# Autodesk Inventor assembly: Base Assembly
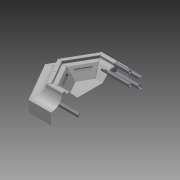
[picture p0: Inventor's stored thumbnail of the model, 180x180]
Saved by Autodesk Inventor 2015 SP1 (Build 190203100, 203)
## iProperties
Created: 2014-12
Part Number: Base Assembly
Document SubType Name: Assembly
Designer: rsheridan
Author: rsheridan
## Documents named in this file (5)
- \\psf\Home\Documents\Inventor\Sau Paulo Chimnea\Base Assembly.iam
- \\psf\Home\Documents\Inventor\Sau Paulo Chimnea\Outer Base and Frame\Frame\Frame0001.iam
- \\psf\Home\Documents\Inventor\Sau Paulo Chimnea\Outer Base.iam
- \\psf\Home\Documents\Inventor\Sau Paulo Chimnea\Fire Tray.ipt
- \\psf\Home\Documents\Inventor\Sau Paulo Chimnea\Base Assembly\Design Accelerator\Bolted Connection1.iam
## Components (4 placed, 4 different names)
1. Frame0001:1 [sub-assembly] — Mate:3
2. Outer Base:1 [sub-assembly] — Mate:1, Mate:2, Mate:3, Mate:5, Mate:6, Flush:1
3. Fire Tray:1 — Mate:5, Mate:6, Flush:1, Mate:7, Mate:8
4. Bolted Connection:1 [sub-assembly] — Mate:7, Mate:8
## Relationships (8: Mate 7, Flush 1)
- Mate:1: Outer Base:1
- Mate:2: Outer Base:1
- Mate:3: Frame0001:1 ↔ Outer Base:1
- Mate:5: Outer Base:1 ↔ Fire Tray:1
- Mate:6: Outer Base:1 ↔ Fire Tray:1
- Flush:1: Outer Base:1 ↔ Fire Tray:1
- Mate:7: Fire Tray:1 ↔ Bolted Connection:1
- Mate:8: Fire Tray:1 ↔ Bolted Connection:1
